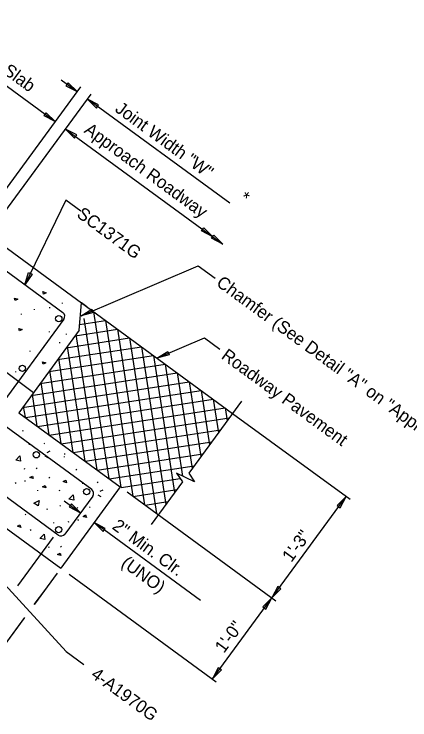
# Model space of a CAD drawing. Extents: x 1970654 to 1970899, y 796145 to 796378.
# Drawn here: x 1970824.47 to 1970840.2, y 796221.12 to 796249.2 of the extents above; entities that cross this region are included whole.
import ezdxf

# ---------------------------------------------------------------- set-up
doc = ezdxf.new("R2010")
doc.units = 0
for name, color, linetype in [('BR_AUTO DIMENSION', 7, 'Continuous'), ('BR_CONCRETE', 7, 'Continuous'), ('BR_DETAILS', 7, 'Continuous'), ('BR_REBAR', 7, 'Continuous'), ('BR_TABLE LINES', 7, 'Continuous'), ('BR_TEXT', 7, 'Continuous')]:
    doc.layers.add(name, color=color, linetype=linetype)

# ---------------------------------------------------------------- blocks, each defined once
blk = doc.blocks.new('B')
at = {"layer": 'BR_AUTO DIMENSION'}
blk.add_lwpolyline([(-0.2, 0.03), (0, 0), (-0.2, -0.03)], close=True, dxfattribs=at)
blk = doc.blocks.new('ARROW')
at = {"layer": 'BR_AUTO DIMENSION', "xscale": 0.625, "yscale": 0.625}
blk.add_blockref('B', (0, 0), dxfattribs=at)
blk = doc.blocks.new('DAH')
at = {"layer": 'BR_AUTO DIMENSION'}
for p in [(-0.1248, 0), (0, 0)]:
    blk.add_blockref('ARROW', p, dxfattribs=at)

msp = doc.modelspace()

# ---------------------------------------------------------------- linework, layer by layer
at = {"layer": 'BR_AUTO DIMENSION'}
for p, q in [((1970820.265, 796249.202), (1970826.108, 796244.924)), ((1970826.336, 796246.59), (1970826.981, 796246.117)), ((1970823.084, 796240.794), (1970827.126, 796246.315)), ((1970823.487, 796240.499), (1970827.529, 796246.02)), ((1970833.044, 796241.678), (1970827.384, 796245.822)), ((1970826.511, 796244.629), (1970832.768, 796240.048)), ((1970826.531, 796241.8), (1970824.898, 796238.433)), ((1970827.125, 796241.365), (1970826.531, 796241.8)), ((1970827.132, 796237.204), (1970831.787, 796239.192)), ((1970831.787, 796239.192), (1970832.464, 796238.697)), ((1970830.147, 796235.52), (1970832.032, 796236.325)), ((1970832.032, 796236.325), (1970832.652, 796235.871)), ((1970833.154, 796233.318), (1970837.824, 796229.899)), ((1970818.822, 796232.27), (1970826.545, 796223.839)), ((1970828.962, 796230.191), (1970834.87, 796225.865)), ((1970832.352, 796222.751), (1970837.669, 796230.013)), ((1970826.464, 796229.837), (1970827.109, 796229.365)), ((1970831.882, 796225.87), (1970827.647, 796228.971)), ((1970826.026, 796228.396), (1970824.604, 796226.454)), ((1970826.177, 796226.962), (1970825.276, 796225.731)), ((1970826.663, 796226.916), (1970832.507, 796222.637)), ((1970825.675, 796226.277), (1970825.26, 796225.71)), ((1970824.86, 796225.163), (1970822.737, 796222.264)), ((1970824.888, 796225.202), (1970823.386, 796223.151)), ((1970826.545, 796223.839), (1970827.238, 796223.332))]:
    msp.add_line(p, q, dxfattribs=at)
for points in [[(1970826.533, 796246.352), (1970826.981, 796246.117), (1970826.622, 796246.473)], [(1970827.832, 796245.587), (1970827.384, 796245.822), (1970827.744, 796245.466)], [(1970825.749, 796245.28), (1970826.108, 796244.924), (1970825.66, 796245.159)], [(1970826.959, 796244.394), (1970826.511, 796244.629), (1970826.87, 796244.273)], [(1970825.184, 796238.851), (1970824.898, 796238.433), (1970825.049, 796238.916)], [(1970827.621, 796237.331), (1970827.132, 796237.204), (1970827.562, 796237.469)], [(1970830.636, 796235.648), (1970830.147, 796235.52), (1970830.577, 796235.785)], [(1970837.434, 796229.565), (1970837.669, 796230.013), (1970837.313, 796229.654)], [(1970826.662, 796229.599), (1970827.109, 796229.365), (1970826.75, 796229.72)], [(1970828.095, 796228.736), (1970827.647, 796228.971), (1970828.006, 796228.615)], [(1970834.95, 796226.426), (1970834.715, 796225.979), (1970835.071, 796226.338)], [(1970834.48, 796225.531), (1970834.715, 796225.979), (1970834.359, 796225.62)], [(1970832.587, 796223.199), (1970832.352, 796222.751), (1970832.708, 796223.11)]]:
    msp.add_lwpolyline(points, close=True, dxfattribs=at)
at = {"layer": 'BR_CONCRETE'}
for p, q in [((1970823.64, 796240.284), (1970827.153, 796237.712)), ((1970827.053, 796236.623), (1970827.153, 796237.712)), ((1970827.053, 796236.623), (1970824.653, 796233.345)), ((1970814.222, 796236.025), (1970826.325, 796227.164)), ((1970823.899, 796235.137), (1970825.244, 796234.152)), ((1970824.653, 796233.345), (1970828.687, 796230.392)), ((1970828.687, 796230.392), (1970826.325, 796227.164))]:
    msp.add_line(p, q, dxfattribs=at)
at = {"layer": 'BR_DETAILS'}
for p, q in [((1970825.89, 796237.509), (1970825.891, 796237.539)), ((1970826.396, 796237.688), (1970826.398, 796237.718)), ((1970824.769, 796237.252), (1970824.771, 796237.282)), ((1970825.276, 796237.431), (1970825.277, 796237.461)), ((1970825.873, 796236.545), (1970825.874, 796236.575)), ((1970826.286, 796236.117), (1970826.287, 796236.147)), ((1970825.112, 796235.775), (1970825.113, 796235.805)), ((1970824.538, 796234.955), (1970824.54, 796234.985)), ((1970833.51, 796233.805), (1970831.415, 796230.943)), ((1970824.809, 796232.62), (1970824.844, 796232.641)), ((1970825.071, 796232.098), (1970825.07, 796232.068)), ((1970825.661, 796232.115), (1970825.697, 796232.135)), ((1970825.819, 796231.547), (1970825.705, 796231.617)), ((1970825.782, 796231.768), (1970825.902, 796231.827)), ((1970826.461, 796231.603), (1970826.46, 796231.573)), ((1970826.48, 796231.715), (1970826.479, 796231.685)), ((1970824.887, 796231.123), (1970824.869, 796231.09)), ((1970825.35, 796231.125), (1970825.385, 796231.146)), ((1970826.922, 796231.073), (1970826.958, 796231.093)), ((1970825.855, 796230.756), (1970825.89, 796230.776)), ((1970824.513, 796230.546), (1970824.548, 796230.566)), ((1970824.893, 796230.65), (1970824.892, 796230.62)), ((1970824.901, 796230.632), (1970824.9, 796230.602)), ((1970827.185, 796230.551), (1970827.184, 796230.521)), ((1970827.775, 796230.567), (1970827.811, 796230.588)), ((1970831.158, 796230.592), (1970829.919, 796228.9)), ((1970825.406, 796230.263), (1970825.404, 796230.233)), ((1970826.264, 796230.244), (1970826.3, 796230.265)), ((1970827.896, 796230.221), (1970828.016, 796230.279)), ((1970827.932, 796230), (1970827.818, 796230.069)), ((1970826.285, 796229.631), (1970826.32, 796229.651)), ((1970825.774, 796229.504), (1970825.809, 796229.524)), ((1970827.001, 796229.575), (1970826.982, 796229.543)), ((1970827.463, 796229.578), (1970827.499, 796229.598)), ((1970824.906, 796229.288), (1970824.941, 796229.308)), ((1970827.007, 796229.102), (1970827.005, 796229.072)), ((1970827.015, 796229.085), (1970827.013, 796229.055)), ((1970826.036, 796228.982), (1970826.035, 796228.952)), ((1970826.626, 796228.998), (1970826.662, 796229.019)), ((1970825.116, 796228.676), (1970825.151, 796228.696)), ((1970825.852, 796228.007), (1970825.834, 796227.974)), ((1970826.315, 796228.009), (1970826.35, 796228.029))]:
    msp.add_line(p, q, dxfattribs=at)
for points in [[(1970825.741, 796238.118), (1970825.639, 796238.064), (1970825.608, 796238.163), (1970825.741, 796238.118)], [(1970824.62, 796237.861), (1970824.518, 796237.806), (1970824.488, 796237.906), (1970824.62, 796237.861)], [(1970824.787, 796236.656), (1970824.685, 796236.602), (1970824.655, 796236.701), (1970824.787, 796236.656)], [(1970825.727, 796235.328), (1970825.625, 796235.274), (1970825.595, 796235.373), (1970825.727, 796235.328)], [(1970824.534, 796231.458), (1970824.701, 796231.63), (1970824.73, 796231.418), (1970824.538, 796231.457)], [(1970825.098, 796230.768), (1970825.2, 796230.822), (1970825.23, 796230.723), (1970825.098, 796230.768)], [(1970831.415, 796230.943), (1970831.64, 796230.598), (1970830.932, 796230.937), (1970831.158, 796230.592)], [(1970826.425, 796230.604), (1970826.527, 796230.658), (1970826.557, 796230.559), (1970826.425, 796230.604)], [(1970825.603, 796230.398), (1970825.705, 796230.453), (1970825.735, 796230.353), (1970825.603, 796230.398)], [(1970826.647, 796229.91), (1970826.815, 796230.083), (1970826.844, 796229.871), (1970826.651, 796229.909)], [(1970825.254, 796229.745), (1970825.47, 796229.85), (1970825.425, 796229.641), (1970825.257, 796229.743)], [(1970827.212, 796229.22), (1970827.314, 796229.275), (1970827.344, 796229.175), (1970827.212, 796229.22)], [(1970824.601, 796228.825), (1970824.703, 796228.879), (1970824.733, 796228.779), (1970824.601, 796228.825)], [(1970825.499, 796228.342), (1970825.666, 796228.514), (1970825.695, 796228.302), (1970825.503, 796228.34)], [(1970826.196, 796227.707), (1970826.298, 796227.761), (1970826.329, 796227.662), (1970826.196, 796227.707)]]:
    msp.add_lwpolyline(points, dxfattribs=at)
at = {"layer": 'BR_REBAR'}
for p, q in [((1970823.886, 796239.174), (1970826.407, 796237.328)), ((1970827.556, 796230.291), (1970816.923, 796238.075)), ((1970826.448, 796237.067), (1970822.194, 796231.256)), ((1970826.226, 796228.475), (1970815.502, 796236.327)), ((1970827.596, 796230.029), (1970826.489, 796228.516))]:
    msp.add_line(p, q, dxfattribs=at)
for centre in [(1970826.248, 796237.085), (1970824.801, 796235.109), (1970825.354, 796231.671), (1970827.352, 796230.207), (1970826.245, 796228.694)]:
    msp.add_circle(centre, 0.125, dxfattribs=at)
for centre, radius, start, end in [((1970826.297, 796237.177), 0.188, 323.7906, 53.7906), ((1970827.445, 796230.139), 0.187, 323.7906, 53.7906), ((1970826.337, 796228.627), 0.187, 233.7906, 323.7906)]:
    msp.add_arc(centre, radius, start, end, dxfattribs=at)
at = {"layer": 'BR_TABLE LINES'}
for p, q in [((1970827.153, 796237.712), (1970833.154, 796233.318)), ((1970827.362, 796237.559), (1970827.153, 796237.712)), ((1970827.628, 796237.364), (1970828.709, 796230.376)), ((1970827.074, 796236.856), (1970828.104, 796237.016)), ((1970827.248, 796237.095), (1970828.234, 796230.724)), ((1970828.104, 796237.016), (1970829.185, 796230.028)), ((1970826.895, 796236.407), (1970828.579, 796236.668)), ((1970828.579, 796236.668), (1970829.66, 796229.68)), ((1970826.554, 796236.457), (1970826.555, 796236.487)), ((1970826.926, 796236.45), (1970827.758, 796231.072)), ((1970826.547, 796235.932), (1970829.055, 796236.319)), ((1970829.055, 796236.319), (1970830.135, 796229.331)), ((1970826.199, 796235.456), (1970829.53, 796235.971)), ((1970826.578, 796235.975), (1970827.283, 796231.42)), ((1970829.53, 796235.971), (1970830.501, 796229.695)), ((1970825.851, 796234.981), (1970830.006, 796235.623)), ((1970830.006, 796235.623), (1970830.849, 796230.17)), ((1970825.502, 796234.505), (1970830.481, 796235.275)), ((1970826.23, 796235.499), (1970826.807, 796231.768)), ((1970830.481, 796235.275), (1970831.17, 796230.823)), ((1970825.882, 796235.024), (1970826.332, 796232.116)), ((1970825.154, 796234.03), (1970830.957, 796234.927)), ((1970830.957, 796234.927), (1970831.545, 796231.121)), ((1970824.806, 796233.554), (1970831.432, 796234.579)), ((1970825.534, 796234.548), (1970825.856, 796232.464)), ((1970831.432, 796234.579), (1970831.893, 796231.596)), ((1970824.919, 796233.15), (1970831.907, 796234.231)), ((1970831.907, 796234.231), (1970832.241, 796232.072)), ((1970825.186, 796234.073), (1970825.381, 796232.812)), ((1970825.395, 796232.802), (1970832.383, 796233.883)), ((1970832.383, 796233.883), (1970832.589, 796232.547)), ((1970824.838, 796233.598), (1970824.905, 796233.161)), ((1970825.87, 796232.454), (1970832.858, 796233.535)), ((1970832.858, 796233.535), (1970832.938, 796233.023)), ((1970826.346, 796232.106), (1970833.022, 796233.138)), ((1970826.821, 796231.758), (1970832.674, 796232.663)), ((1970827.297, 796231.41), (1970832.326, 796232.188)), ((1970827.772, 796231.062), (1970831.978, 796231.712)), ((1970828.248, 796230.714), (1970831.63, 796231.237)), ((1970828.723, 796230.366), (1970831.069, 796230.728)), ((1970829.199, 796230.017), (1970830.934, 796230.286)), ((1970829.674, 796229.669), (1970830.586, 796229.81))]:
    msp.add_line(p, q, dxfattribs=at)

# ---------------------------------------------------------------- block references
at = {"layer": 'BR_TEXT', "xscale": 4.00000005, "yscale": 4.000000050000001, "rotation": -36.209418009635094}
msp.add_blockref('DAH', (1970832.768, 796240.048), dxfattribs=at)

# ---------------------------------------------------------------- texts
at = {"layer": 'BR_AUTO DIMENSION'}
for s, rotation, p in [('Joint Width "W"', 323.7906, (1970828.447, 796245.354)), ('2" Min. Clr. ', 323.7906, (1970828.333, 796228.751)), ('1\'-3"', 53.7906, (1970835.491, 796227.365)), ('(UNO)', 323.7906, (1970828.69, 796227.275)), ('1\'-0"', 53.7906, (1970832.811, 796223.75))]:
    msp.add_text(s, height=0.5, rotation=rotation, dxfattribs=at).set_placement(p)
at = {"layer": 'BR_TEXT'}
for s, height, p in [('Approach Slab', 0.49995, (1970821.542, 796248.665)), ('Approach Roadway', 0.49995, (1970827.219, 796244.512)), ('*', 0.5, (1970833.389, 796241.786)), (' SC1371G', 0.4999, (1970826.773, 796241.271)), ('Chamfer (See Detail "A" on "Approach Slab No. 3" sheet)', 0.49995, (1970832.47, 796238.427)), ('Roadway Pavement', 0.49995, (1970832.668, 796235.526)), ('4-A1970G', 0.4999, (1970827.49, 796222.843))]:
    msp.add_text(s, height=height, rotation=323.7906, dxfattribs=at).set_placement(p)

doc.saveas('drawing.dxf')
